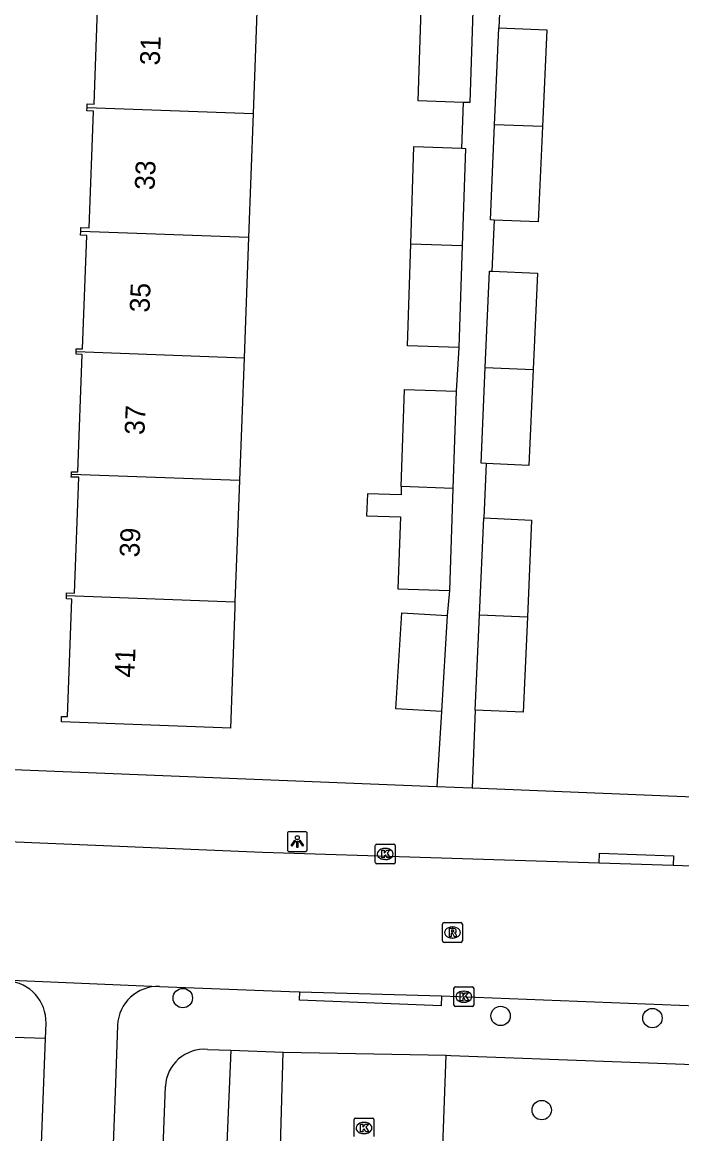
# Model space of a CAD drawing. Extents: x 160077 to 160945, y 386481 to 387498.
# Drawn here: x 160622.7 to 160655.9, y 386603 to 386659.1 of the extents above; entities that cross this region are included whole.
import ezdxf

# ---------------------------------------------------------------- set-up
doc = ezdxf.new("R2010")
doc.units = 0
for name, color, linetype in [('IMGEO_Boom', 7, 'Continuous'), ('IMGEO_Fietspad_open', 7, 'Continuous'), ('IMGEO_Groenvoorziening', 7, 'Continuous'), ('IMGEO_Kolk', 7, 'Continuous'), ('IMGEO_Lichtpunt', 7, 'Continuous'), ('IMGEO_Pand', 7, 'Continuous'), ('IMGEO_Pand_nummerreeks', 7, 'Continuous'), ('IMGEO_Rijbaan_lokaal_open', 7, 'Continuous'), ('IMGEO_Rioolput', 7, 'Continuous'), ('IMGEO_Voetpad_open', 7, 'Continuous')]:
    doc.layers.add(name, color=color, linetype=linetype)

msp = doc.modelspace()

# ---------------------------------------------------------------- linework, layer by layer
at = {"layer": 'IMGEO_Boom'}
for centre in [(160630.749, 386609.895), (160646.773, 386608.993), (160654.429, 386608.885), (160648.846, 386604.245)]:
    msp.add_circle(centre, 0.489, dxfattribs=at)
at = {"layer": 'IMGEO_Fietspad_open'}
for points in [[(160623.826, 386607.863), (160623.855, 386608.623)], [(160627.454, 386608.528), (160627.347, 386605.61), (160624.634, 386534.751), (160624.537, 386532.454), (160624.477, 386529.933)], [(160622.55, 386582.717), (160622.865, 386582.684), (160623.826, 386607.863)]]:
    msp.add_lwpolyline(points, dxfattribs=at)
for centre, radius, start, end in [((160621.762, 386608.674), 2.093, 358.5926, 85.4055), ((160629.505, 386608.428), 2.054, 88.0303, 177.2201)]:
    msp.add_arc(centre, radius, start, end, dxfattribs=at)
at = {"layer": 'IMGEO_Groenvoorziening'}
msp.add_lwpolyline([(160633.166, 386607.264), (160632.08, 386581.72)], dxfattribs=at)
at = {"layer": 'IMGEO_Kolk'}
for p, q in [((160640.456, 386616.737), (160640.456, 386617.589)), ((160640.531, 386617.663), (160641.383, 386617.663)), ((160640.944, 386617.443), (160640.969, 386617.443)), ((160641.457, 386617.589), (160641.457, 386616.737)), ((160641.383, 386616.663), (160640.531, 386616.663)), ((160640.967, 386616.883), (160640.942, 386616.883)), ((160644.418, 386609.538), (160644.418, 386610.39)), ((160644.493, 386610.464), (160645.345, 386610.464)), ((160645.419, 386610.39), (160645.419, 386609.538)), ((160644.906, 386610.244), (160644.931, 386610.244)), ((160645.345, 386609.464), (160644.493, 386609.464)), ((160644.929, 386609.684), (160644.904, 386609.684)), ((160639.385, 386602.915), (160639.385, 386603.767)), ((160639.46, 386603.841), (160640.312, 386603.841)), ((160640.386, 386603.767), (160640.386, 386602.915)), ((160639.873, 386603.621), (160639.898, 386603.621)), ((160639.896, 386603.061), (160639.871, 386603.061))]:
    msp.add_line(p, q, dxfattribs=at)
for points in [[(160640.456, 386616.737), (160640.456, 386617.589)], [(160640.531, 386617.663), (160641.383, 386617.663)], [(160640.777, 386617.363), (160640.9, 386617.363), (160640.9, 386617.212), (160641.03, 386617.363), (160641.194, 386617.363), (160641.048, 386617.212), (160641.201, 386616.963), (160641.049, 386616.963), (160640.964, 386617.127), (160640.9, 386617.06), (160640.9, 386616.963), (160640.777, 386616.963), (160640.777, 386617.363)], [(160641.457, 386617.589), (160641.457, 386616.737)], [(160641.383, 386616.663), (160640.531, 386616.663)], [(160644.418, 386609.538), (160644.418, 386610.39)], [(160644.493, 386610.464), (160645.345, 386610.464)], [(160645.419, 386610.39), (160645.419, 386609.538)], [(160644.739, 386610.164), (160644.862, 386610.164), (160644.862, 386610.013), (160644.992, 386610.164), (160645.156, 386610.164), (160645.01, 386610.013), (160645.163, 386609.764), (160645.011, 386609.764), (160644.926, 386609.928), (160644.862, 386609.861), (160644.862, 386609.764), (160644.739, 386609.764), (160644.739, 386610.164)], [(160645.345, 386609.464), (160644.493, 386609.464)], [(160639.385, 386602.915), (160639.385, 386603.767)], [(160639.46, 386603.841), (160640.312, 386603.841)], [(160640.386, 386603.767), (160640.386, 386602.915)], [(160639.706, 386603.541), (160639.829, 386603.541), (160639.829, 386603.39), (160639.959, 386603.541), (160640.123, 386603.541), (160639.977, 386603.39), (160640.13, 386603.141), (160639.978, 386603.141), (160639.893, 386603.305), (160639.829, 386603.238), (160639.829, 386603.141), (160639.706, 386603.141), (160639.706, 386603.541)]]:
    msp.add_lwpolyline(points, dxfattribs=at)
for centre, start, end in [((160640.533, 386617.587), 91.552, 178.448), ((160640.533, 386617.587), 91.552, 178.448), ((160641.381, 386617.587), 1.552, 88.448), ((160641.381, 386617.587), 1.552, 88.448), ((160640.533, 386616.739), 181.552, 268.448), ((160640.533, 386616.739), 181.552, 268.448), ((160641.381, 386616.739), 271.552, 358.448), ((160641.381, 386616.739), 271.552, 358.448), ((160644.495, 386610.388), 91.552, 178.448), ((160644.495, 386610.388), 91.552, 178.448), ((160645.343, 386610.388), 1.552, 88.448), ((160645.343, 386610.388), 1.552, 88.448), ((160644.495, 386609.54), 181.552, 268.448), ((160644.495, 386609.54), 181.552, 268.448), ((160645.343, 386609.54), 271.552, 358.448), ((160645.343, 386609.54), 271.552, 358.448), ((160639.462, 386603.765), 91.552, 178.448), ((160639.462, 386603.765), 91.552, 178.448), ((160640.31, 386603.765), 1.552, 88.448), ((160640.31, 386603.765), 1.552, 88.448)]:
    msp.add_arc(centre, 0.0765, start, end, dxfattribs=at)
for centre, major_axis, ratio, start_param, end_param in [((160640.943, 386617.163), (-0.387, 0.002), 0.722429, 4.712389, 7.853982), ((160640.968, 386617.163), (-0.39, 0.002), 0.717154, 1.570796, 4.712389), ((160644.905, 386609.964), (-0.387, 0.002), 0.722429, 4.712389, 7.853982), ((160644.93, 386609.964), (-0.39, 0.002), 0.717154, 1.570796, 4.712389), ((160639.872, 386603.341), (-0.387, 0.002), 0.722429, 4.712389, 7.853982), ((160639.897, 386603.341), (-0.39, 0.002), 0.717154, 1.570796, 4.712389)]:
    msp.add_ellipse(centre, major_axis=major_axis, ratio=ratio, start_param=start_param, end_param=end_param, dxfattribs=at)
at = {"layer": 'IMGEO_Lichtpunt'}
for p, q in [((160636.926, 386618.285), (160636.118, 386618.285)), ((160636.926, 386618.285), (160636.118, 386618.285)), ((160636.024, 386618.19), (160636.024, 386617.383)), ((160636.024, 386618.19), (160636.024, 386617.383)), ((160637.02, 386617.383), (160637.02, 386618.19)), ((160637.02, 386617.383), (160637.02, 386618.19)), ((160636.118, 386617.289), (160636.926, 386617.289)), ((160636.118, 386617.289), (160636.926, 386617.289))]:
    msp.add_line(p, q, dxfattribs=at)
for points in [[(160636.398, 386617.854), (160636.437, 386617.826), (160636.249, 386617.564), (160636.211, 386617.591), (160636.398, 386617.854)], [(160636.5, 386617.806), (160636.547, 386617.806), (160636.547, 386617.484), (160636.5, 386617.484), (160636.5, 386617.806)], [(160636.61, 386617.826), (160636.648, 386617.853), (160636.835, 386617.591), (160636.796, 386617.563), (160636.61, 386617.826)]]:
    msp.add_lwpolyline(points, dxfattribs=at)
msp.add_circle((160636.523, 386617.988), 0.0994, dxfattribs=at)
for centre, start, end in [((160636.118, 386618.19), 90, 180), ((160636.118, 386618.19), 90, 180), ((160636.926, 386618.19), 0, 90), ((160636.926, 386618.19), 0, 90), ((160636.118, 386617.383), 180, 270), ((160636.118, 386617.383), 180, 270), ((160636.926, 386617.383), 270, 0), ((160636.926, 386617.383), 270, 360)]:
    msp.add_arc(centre, 0.0946, start, end, dxfattribs=at)
at = {"layer": 'IMGEO_Pand'}
for points in [[(160625.918, 386654.825), (160625.924, 386654.998), (160626.274, 386654.985), (160626.488, 386660.762), (160626.144, 386660.774), (160626.15, 386660.922)], [(160634.516, 386660.611), (160634.291, 386654.514)], [(160644.881, 386655.077), (160642.615, 386655.151), (160642.785, 386660.304)], [(160645.384, 386660.207), (160645.214, 386655.066), (160644.881, 386655.077)], [(160646.468, 386653.953), (160646.682, 386658.842)], [(160646.682, 386658.842), (160649.099, 386658.736), (160648.885, 386653.859)], [(160625.605, 386648.568), (160625.612, 386648.758), (160626.03, 386648.743), (160626.248, 386654.636), (160625.911, 386654.649), (160625.918, 386654.825)], [(160625.918, 386654.825), (160634.291, 386654.514)], [(160634.291, 386654.514), (160634.059, 386648.254)], [(160646.446, 386649.143), (160646.257, 386649.151), (160646.468, 386653.953)], [(160648.885, 386653.859), (160648.674, 386649.045), (160646.446, 386649.143)], [(160648.885, 386653.859), (160646.468, 386653.953)], [(160642.24, 386647.95), (160642.401, 386652.845), (160644.804, 386652.765)], [(160644.804, 386652.765), (160645, 386652.759), (160644.839, 386647.854)], [(160625.368, 386642.51), (160625.374, 386642.652), (160625.692, 386642.64), (160625.903, 386648.366), (160625.598, 386648.377), (160625.605, 386648.568)], [(160634.059, 386648.254), (160625.605, 386648.568)], [(160634.059, 386648.254), (160633.836, 386642.196)], [(160644.669, 386642.712), (160642.07, 386642.797), (160642.24, 386647.95)], [(160642.24, 386647.95), (160644.839, 386647.854)], [(160644.839, 386647.854), (160644.669, 386642.712)], [(160645.998, 386641.701), (160646.211, 386646.563), (160646.333, 386646.558)], [(160646.333, 386646.558), (160648.628, 386646.457), (160648.415, 386641.601)], [(160625.132, 386636.312), (160625.137, 386636.447), (160625.447, 386636.436), (160625.666, 386642.361), (160625.363, 386642.372), (160625.368, 386642.51)], [(160625.368, 386642.51), (160633.836, 386642.196)], [(160633.836, 386642.196), (160633.607, 386635.997)], [(160646.04, 386636.861), (160645.786, 386636.872), (160645.998, 386641.701)], [(160645.998, 386641.701), (160648.415, 386641.601)], [(160648.415, 386641.601), (160648.203, 386636.766), (160646.04, 386636.861)], [(160641.767, 386635.694), (160641.928, 386640.589), (160644.527, 386640.503)], [(160644.527, 386640.503), (160644.366, 386635.597)], [(160624.887, 386630.182), (160624.892, 386630.329), (160625.282, 386630.315), (160625.498, 386636.164), (160625.127, 386636.178), (160625.132, 386636.312)], [(160633.607, 386635.997), (160625.132, 386636.312)], [(160633.607, 386635.997), (160633.38, 386629.867)], [(160641.767, 386635.694), (160641.753, 386635.282), (160640.055, 386635.338), (160640.018, 386634.225), (160641.717, 386634.17), (160641.597, 386630.541), (160644.196, 386630.456)], [(160644.366, 386635.597), (160641.767, 386635.694)], [(160644.366, 386635.597), (160644.196, 386630.456)], [(160645.705, 386629.212), (160645.92, 386634.117)], [(160645.92, 386634.117), (160648.337, 386634.011), (160648.122, 386629.118)], [(160633.38, 386629.867), (160633.371, 386629.615), (160633.145, 386623.508), (160632.741, 386623.523), (160624.626, 386623.822), (160624.637, 386624.104), (160624.94, 386624.093), (160625.159, 386630.024), (160624.881, 386630.034), (160624.887, 386630.182)], [(160633.38, 386629.867), (160624.887, 386630.182)], [(160643.79, 386624.351), (160641.497, 386624.488), (160641.786, 386629.33), (160644.079, 386629.193)], [(160644.079, 386629.193), (160643.79, 386624.351)], [(160645.495, 386624.426), (160645.705, 386629.212)], [(160648.122, 386629.118), (160647.912, 386624.32), (160645.495, 386624.426)], [(160648.122, 386629.118), (160645.705, 386629.212)]]:
    msp.add_lwpolyline(points, dxfattribs=at)
at = {"layer": 'IMGEO_Rijbaan_lokaal_open'}
for points in [[(160651.75, 386616.707), (160634.763, 386617.242), (160621.528, 386617.801)], [(160655.471, 386616.575), (160651.75, 386616.707)], [(160664.809, 386616.246), (160655.471, 386616.575)], [(160621.303, 386610.835), (160629.576, 386610.481)], [(160629.576, 386610.481), (160636.136, 386610.219), (160636.654, 386610.205)], [(160636.654, 386610.205), (160643.793, 386610.008)], [(160643.793, 386610.008), (160660.074, 386609.377)], [(160635.084, 386581.608), (160635.811, 386607.172)], [(160635.811, 386607.172), (160644.033, 386607.016)], [(160643.789, 386600.571), (160644.033, 386607.016)]]:
    msp.add_lwpolyline(points, dxfattribs=at)
at = {"layer": 'IMGEO_Rioolput'}
for p, q in [((160643.844, 386612.777), (160643.844, 386613.629)), ((160643.919, 386613.703), (160644.771, 386613.703)), ((160644.332, 386613.483), (160644.357, 386613.483)), ((160644.845, 386613.629), (160644.845, 386612.777)), ((160644.771, 386612.703), (160643.919, 386612.703)), ((160644.355, 386612.923), (160644.33, 386612.923))]:
    msp.add_line(p, q, dxfattribs=at)
for points in [[(160643.844, 386612.777), (160643.844, 386613.629)], [(160643.919, 386613.703), (160644.771, 386613.703)], [(160644.433, 386613.401), (160644.181, 386613.403), (160644.181, 386613.003)], [(160644.359, 386613.322), (160644.305, 386613.322), (160644.305, 386613.241)], [(160644.305, 386613.241), (160644.357, 386613.241)], [(160644.845, 386613.629), (160644.845, 386612.777)], [(160644.771, 386612.703), (160643.919, 386612.703)], [(160644.181, 386613.003), (160644.305, 386613.003), (160644.305, 386613.165), (160644.316, 386613.165)], [(160644.363, 386613.136), (160644.434, 386613.003), (160644.574, 386613.003), (160644.509, 386613.129)]]:
    msp.add_lwpolyline(points, dxfattribs=at)
for centre, radius, start, end in [((160643.921, 386613.627), 0.0765, 91.552, 178.448), ((160643.921, 386613.627), 0.0765, 91.552, 178.448), ((160644.341, 386613.43), 0.19, 274.7715, 282.9687), ((160644.365, 386613.226), 0.0964, 77.0061, 93.1865), ((160644.379, 386613.283), 0.0378, 276.6634, 79.6772), ((160644.432, 386613.291), 0.109, 350.3612, 89.416), ((160644.43, 386613.291), 0.112, 277.5842, 350.9817), ((160644.769, 386613.627), 0.0765, 1.552, 88.448), ((160644.769, 386613.627), 0.0765, 1.552, 88.448), ((160643.921, 386612.779), 0.0765, 181.552, 268.448), ((160643.921, 386612.779), 0.0765, 181.552, 268.448), ((160644.315, 386613.112), 0.0533, 26.0293, 88.6989), ((160644.414, 386613.076), 0.108, 29.5134, 73.7905), ((160644.769, 386612.779), 0.0765, 271.552, 358.448), ((160644.769, 386612.779), 0.0765, 271.552, 358.448)]:
    msp.add_arc(centre, radius, start, end, dxfattribs=at)
for centre, major_axis, ratio, start_param, end_param in [((160644.331, 386613.203), (-0.387, 0.002), 0.722429, 4.712389, 7.853982), ((160644.356, 386613.203), (-0.39, 0.002), 0.717154, 1.570796, 4.712389)]:
    msp.add_ellipse(centre, major_axis=major_axis, ratio=ratio, start_param=start_param, end_param=end_param, dxfattribs=at)
at = {"layer": 'IMGEO_Voetpad_open'}
for points in [[(160646.796, 386661.44), (160646.682, 386658.842)], [(160644.881, 386655.077), (160644.804, 386652.765)], [(160646.446, 386649.143), (160646.333, 386646.558)], [(160644.669, 386642.712), (160644.527, 386640.503)], [(160646.04, 386636.861), (160645.92, 386634.117)], [(160644.196, 386630.456), (160644.079, 386629.193)], [(160645.495, 386624.426), (160645.337, 386620.494)], [(160643.79, 386624.351), (160643.564, 386620.565)], [(160621.359, 386621.46), (160643.564, 386620.565)], [(160643.564, 386620.565), (160645.337, 386620.494)], [(160645.337, 386620.494), (160665.983, 386619.662)], [(160651.75, 386616.707), (160651.768, 386617.206), (160655.489, 386617.074), (160655.471, 386616.575)], [(160643.793, 386610.008), (160643.774, 386609.51), (160636.638, 386609.786), (160636.654, 386610.205)], [(160623.826, 386607.863), (160604.913, 386608.442)], [(160631.986, 386607.305), (160633.166, 386607.264)], [(160633.166, 386607.264), (160635.811, 386607.172)], [(160644.033, 386607.016), (160644.27, 386607.006), (160660.561, 386606.393)], [(160628.965, 386581.812), (160629.874, 386605.451)]]:
    msp.add_lwpolyline(points, dxfattribs=at)
msp.add_arc((160631.834, 386605.348), 1.963, 85.5644, 176.9916, dxfattribs=at)

# ---------------------------------------------------------------- texts
at = {"layer": 'IMGEO_Pand_nummerreeks'}
for s, rotation, p in [('31', 87.6336, (160629.581, 386656.929)), ('33', 87.6336, (160629.321, 386650.641)), ('35', 87.6336, (160629.065, 386644.465)), ('37', 87.6336, (160628.81, 386638.289)), ('39', 87.6336, (160628.555, 386632.114)), ('41', 87.6339, (160628.305, 386626.051))]:
    msp.add_text(s, height=1, rotation=rotation, dxfattribs=at).set_placement(p)

doc.saveas('drawing.dxf')
